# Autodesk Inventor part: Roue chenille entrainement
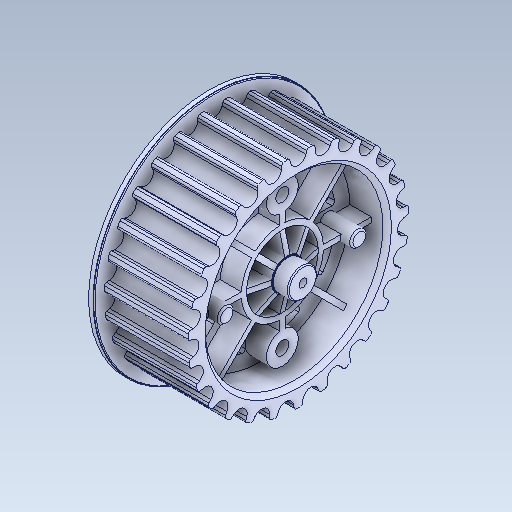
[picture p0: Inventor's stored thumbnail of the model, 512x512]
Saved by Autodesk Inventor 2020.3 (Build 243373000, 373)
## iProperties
Created: 2018-09
Part Number: Roue chenille entrainement
Material: Générique
Document SubType Name: Modeling
Designer: ficho
Density: 1 g/cm^3
Appearance: Par défaut
Mass: 7.77073 g
Surface Area: 114.341 cm^2
Volume: 7.77073 cm^3
Sending System: SolidWorks 2015
Last Author: adrien
Last Saved: 2019-01-10
Author: ficho
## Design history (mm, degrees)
feature "Boss.-Extru.9" [Congé]
feature "Boss.-Extru.12" [Congé]
feature "Congé4"
node "Solide1"
node "Solide2"
node "Solide3"
